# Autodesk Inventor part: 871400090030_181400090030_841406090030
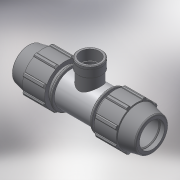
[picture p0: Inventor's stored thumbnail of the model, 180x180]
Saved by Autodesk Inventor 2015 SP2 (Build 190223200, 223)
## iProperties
Created: 2017-02
Part Number: 871400090030_181400090030_841406090030
Material: Generic
Description: PLASSON TEE WITH THREADED FEMALE OFFTAKE 90-3."-90
Document SubType Name: Modeling
Designer: KIM
Mass: 92.6774 g
Surface Area: 199.44 cm^2
Volume: 66.1981 cm^3
Density: 1 g/cm^3
Appearance: Default
Author: KIM
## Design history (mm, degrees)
derived "87140.ipt"
feature "Solid1::87140.ipt"
feature "Solid2::87140.ipt"
tag "TaggingFeature1"
body "Solid1"
other parameters: "d4" = 17.41667, "d5" = 50.16, "d7" = 152, "d11" = 6.96667, "d13" = 120 deg, "d14" = 117, "d15" = 10 deg, "d16" = 132.24, "d18" = 4.5, "d19" = 35 deg, "d20" = 17.5 deg, "d21" = 141.36, "d23" = 0, "d25" = 360 deg, "d27" = 3.04, "d33" = 1.8, "d42" = 75.24, "d43" = 4.56, "d46" = 2.7, "d68" = 12.54, "d72" = 116, "d76" = 84.926, "d80" = 2.54778, "d91" = 114, "d93" = 164, "d95" = 81, "d112" = 41, "d115" = 106.1575, "d116" = 135 deg, "d117" = 97.6649, "d118" = 418, "d119" = 81, "d121" = 0, "d122" = 81, "d124" = 0, "d128" = 0, "d129" = 9, "d130" = 12.3, "d131" = 0.3, "d132" = 0.3, "d133" = 106.1575, "E_" = 152, "A_" = 116, "l_" = 164, "l_2" = 41, "Rp_" = 84.926, "H_" = 418
